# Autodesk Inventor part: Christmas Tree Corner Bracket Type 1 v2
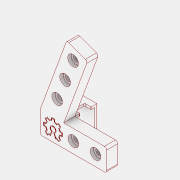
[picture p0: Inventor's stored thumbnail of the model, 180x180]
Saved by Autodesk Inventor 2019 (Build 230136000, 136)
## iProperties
Created: 2025-12
Part Number: Christmas Tree Corner Bracket Type 1 v2
Material: ABS Plastic
Document SubType Name: Modeling
Designer: sab
Density: 1.06 g/cm^3
Appearance: Red
Mass: 24.4978 g
Surface Area: 88.7218 cm^2
Volume: 23.1111 cm^3
Author: sab
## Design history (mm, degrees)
node "Blocks"
  sketch "Block1"
    geometry: L1 (0, 0.5)-(342.02, 940.193); L2 (0, -4.92)-(0, 0); L3 (0, -19.5)-(684.04, -19.5); L4 (21.284, 0.5)-(342.02, 881.717); L5 (0, 0.5)-(684.04, 0.5); L6 (662.757, 0.5)-(342.02, 881.717); L7 (684.04, 0.5)-(342.02, 940.193); L8 (684.04, -4.92)-(684.04, 0); L9 (0, 0.5)-(0, 0); L10 (684.04, 0.5)-(684.04, 0); 1 further point
    constraints: 20 end point
  sketch "Block1_1"
    geometry: L1 (-5.09, 2.943)-(-3.464, 3.257); L2 (-3.464, 3.257)-(-2.886, 4.652); L3 (-2.886, 4.652)-(-3.839, 6.061); L4 (-3.839, 6.061)-(-2.636, 7.264); L5 (-2.636, 7.264)-(-1.238, 6.318); L6 (-1.238, 6.318)-(0.22, 6.922); L7 (0.22, 6.922)-(0.531, 8.532); L8 (0.531, 8.532)-(2.267, 8.532); L9 (2.267, 8.532)-(2.588, 6.869); L10 (2.588, 6.869)-(4.046, 6.265); L11 (4.046, 6.265)-(5.403, 7.184); L12 (5.403, 7.184)-(6.631, 5.956); L13 (6.631, 5.956)-(5.682, 4.554); L14 (5.682, 4.554)-(6.286, 3.096); L15 (6.286, 3.096)-(7.895, 2.785); L16 (7.895, 2.785)-(7.895, 1.05); L17 (7.895, 1.05)-(6.232, 0.729); L18 (6.232, 0.729)-(5.627, -0.731); L19 (5.627, -0.731)-(6.541, -2.081); L20 (6.541, -2.081)-(5.344, -3.279); L21 (5.344, -3.279)-(3.887, -2.293); L22 (3.887, -2.293)-(3.329, -2.524); L23 (3.329, -2.524)-(2.197, 0.247); L24 (0.657, 0.303)-(-0.496, -2.521); L25 (-0.496, -2.521)-(-1.178, -2.239); L26 (-1.178, -2.239)-(-2.536, -3.157); L27 (-2.536, -3.157)-(-3.766, -1.927); L28 (-3.766, -1.927)-(-2.82, -0.529); L29 (-2.82, -0.529)-(-3.42, 0.919); L30 (-3.42, 0.919)-(-5.09, 1.242); L31 (-5.09, 1.242)-(-5.09, 2.943); A1 r 0.085 centre (-3.45, 3.333) between (-3.434, 3.25) and (-3.371, 3.301); A2 r 0.085 centre (-2.899, 4.663) between (-2.82, 4.63) and (-2.828, 4.711); A3 r 0.085 centre (-3.663, 6.098) between (-3.724, 6.158) and (-3.734, 6.05); A4 r 0.085 centre (-2.519, 7.242) between (-2.471, 7.312) and (-2.58, 7.302); A5 r 0.085 centre (-1.085, 6.477) between (-1.132, 6.407) and (-1.052, 6.398); A6 r 0.085 centre (0.245, 7.028) between (0.278, 6.949) and (0.329, 7.012); A7 r 0.085 centre (0.719, 8.583) between (0.719, 8.668) and (0.635, 8.599); A8 r 0.085 centre (2.337, 8.583) between (2.421, 8.599) and (2.337, 8.668); A9 r 0.085 centre (2.811, 7.028) between (2.727, 7.012) and (2.778, 6.949); A10 r 0.085 centre (4.14, 6.477) between (4.108, 6.398) and (4.188, 6.407); A11 r 0.085 centre (5.575, 7.242) between (5.636, 7.302) and (5.527, 7.312); A12 r 0.085 centre (6.719, 6.098) between (6.79, 6.05) and (6.78, 6.158); A13 r 0.085 centre (5.955, 4.663) between (5.884, 4.711) and (5.876, 4.63); A14 r 0.085 centre (6.506, 3.333) between (6.427, 3.301) and (6.489, 3.25); A15 r 0.085 centre (8.06, 2.859) between (8.146, 2.859) and (8.077, 2.943); A16 r 0.085 centre (8.06, 1.242) between (8.077, 1.158) and (8.146, 1.242); A17 r 0.085 centre (6.506, 0.768) between (6.489, 0.851) and (6.427, 0.8); A18 r 0.085 centre (5.955, -0.562) between (5.876, -0.529) and (5.884, -0.61); A19 r 0.085 centre (6.719, -1.997) between (6.78, -2.057) and (6.79, -1.949); A20 r 0.085 centre (5.575, -3.141) between (5.527, -3.212) and (5.636, -3.201); A21 r 0.085 centre (4.14, -2.376) between (4.188, -2.306) and (4.108, -2.297); A22 r 0.085 centre (3.466, -2.471) between (3.387, -2.503) and (3.499, -2.55); A23 r 0.085 centre (2.345, 0.274) between (2.31, 0.352) and (2.266, 0.242); A24 r 1.87 centre (1.489, 1.977) between (2.197, 0.247) and (0.657, 0.303); A25 r 0.085 centre (0.71, 0.274) between (0.79, 0.242) and (0.746, 0.352); A26 r 0.085 centre (-0.41, -2.471) between (-0.443, -2.55) and (-0.331, -2.503); A27 r 0.085 centre (-1.085, -2.376) between (-1.052, -2.297) and (-1.132, -2.306); A28 r 0.085 centre (-2.519, -3.141) between (-2.58, -3.201) and (-2.471, -3.212); A29 r 0.085 centre (-3.663, -1.997) between (-3.734, -1.949) and (-3.724, -2.057); A30 r 0.085 centre (-2.899, -0.562) between (-2.828, -0.61) and (-2.82, -0.529); A31 r 0.085 centre (-3.45, 0.768) between (-3.371, 0.8) and (-3.434, 0.851); A32 r 0.085 centre (-5.005, 1.242) between (-5.09, 1.242) and (-5.021, 1.158); A33 r 0.085 centre (-5.005, 2.859) between (-5.021, 2.943) and (-5.09, 2.859); 1 further point
    constraints: 66 point on circle, 62 end point, 33 centre point
  sketch "Block1_2"
    geometry: L1 (-0.89, -10)-(-0.68, -10.21); L2 (-0.89, -10)-(-0.68, -9.79); L3 (-0.68, -9.79)-(-0.68, -7.161); L4 (-0.68, -7.161)-(1.981, -4.5); L5 (1.981, -4.5)-(3.62, -4.5); L6 (3.62, -4.5)-(3.62, -6.875); L7 (3.62, -6.875)-(3.965, -6.875); L8 (3.965, -6.875)-(5.42, -5.42); L9 (5.42, -5.42)-(5.42, -0.5); L10 (4.92, 0)-(0, 0); L11 (-1.455, -1.455)-(0, 0); L12 (-1.455, -1.8)-(-1.455, -1.455); L13 (0.92, -1.8)-(-1.455, -1.8); L14 (0.92, -3.439)-(0.92, -1.8); L15 (-1.741, -6.1)-(0.92, -3.439); L16 (-4.37, -6.1)-(-1.741, -6.1); L17 (-4.58, -6.31)-(-4.37, -6.1); L18 (-4.58, -6.31)-(-4.79, -6.1); L19 (-4.79, -6.1)-(-7.419, -6.1); L20 (-7.419, -6.1)-(-10.08, -3.439); L21 (-10.08, -3.439)-(-10.08, -1.8); L22 (-10.08, -1.8)-(-7.705, -1.8); L23 (-7.705, -1.8)-(-7.705, -1.455); L24 (-7.705, -1.455)-(-9.16, 0); L25 (-9.16, 0)-(-14.08, 0); L26 (-14.58, -5.42)-(-14.58, -0.5); L27 (-13.125, -6.875)-(-14.58, -5.42); L28 (-12.78, -6.875)-(-13.125, -6.875); L29 (-12.78, -4.5)-(-12.78, -6.875); L30 (-11.141, -4.5)-(-12.78, -4.5); L31 (-8.48, -7.161)-(-11.141, -4.5); L32 (-8.48, -9.79)-(-8.48, -7.161); L33 (-8.27, -10)-(-8.48, -9.79); L34 (-8.27, -10)-(-8.48, -10.21); L35 (-8.48, -10.21)-(-8.48, -12.839); L36 (-8.48, -12.839)-(-11.141, -15.5); L37 (-11.141, -15.5)-(-12.78, -15.5); L38 (-12.78, -15.5)-(-12.78, -13.125); L39 (-12.78, -13.125)-(-13.125, -13.125); L40 (-13.125, -13.125)-(-14.58, -14.58); L41 (-14.58, -19.5)-(-14.58, -14.58); L42 (-9.16, -20)-(-14.08, -20); L43 (-7.705, -18.545)-(-9.16, -20); L44 (-7.705, -18.2)-(-7.705, -18.545); L45 (-10.08, -18.2)-(-7.705, -18.2); L46 (-10.08, -16.561)-(-10.08, -18.2); L47 (-7.419, -13.9)-(-10.08, -16.561); L48 (-4.79, -13.9)-(-7.419, -13.9); L49 (-4.58, -13.69)-(-4.79, -13.9); L50 (-4.58, -13.69)-(-4.37, -13.9); L51 (-4.37, -13.9)-(-1.741, -13.9); L52 (-1.741, -13.9)-(0.92, -16.561); L53 (0.92, -16.561)-(0.92, -18.2); L54 (0.92, -18.2)-(-1.455, -18.2); L55 (-1.455, -18.2)-(-1.455, -18.545); L56 (-1.455, -18.545)-(0, -20); L57 (4.92, -20)-(0, -20); L58 (5.42, -19.5)-(5.42, -14.58); L59 (3.965, -13.125)-(5.42, -14.58); L60 (3.62, -13.125)-(3.965, -13.125); L61 (3.62, -15.5)-(3.62, -13.125); L62 (1.981, -15.5)-(3.62, -15.5); L63 (-0.68, -12.839)-(1.981, -15.5); L64 (-0.68, -10.21)-(-0.68, -12.839)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; C1 r 2.1 at (-4.58, -10); A1 r 0.5 centre (4.92, -0.5) between (5.42, -0.5) and (4.92, 0); A2 r 0.5 centre (-14.08, -0.5) between (-14.08, 0) and (-14.58, -0.5); A3 r 0.5 centre (-14.08, -19.5) between (-14.58, -19.5) and (-14.08, -20); A4 r 0.5 centre (4.92, -19.5) between (4.92, -20) and (5.42, -19.5); A5 r 0.75 centre (4.92, -0.5) between (5.67, -0.5) and (4.92, 0.25); A6 r 0.75 centre (4.92, -19.5) between (4.92, -20.25) and (5.67, -19.5); A7 r 0.75 centre (-14.08, -19.5) between (-14.83, -19.5) and (-14.08, -20.25); A8 r 0.75 centre (-14.08, -0.5) between (-14.08, 0.25) and (-14.83, -0.5); 2 further points
    constraints: 256 end point, 16 point on circle, 9 centre point, 67 other
    dimensions: "d33" = 0.25 distance between parallel lines of L24 L65
sketch "Sketch1"
  geometry: L1 (0, 0)-(21.284, 0); L2 (60, 0)-(60, -20); L3 (60, -20)-(0, -20); L4 (0, -20)-(0, 0); L5 (0, 0)-(23.941, 65.778); L6 (23.941, 65.778)-(42.735, 58.938); L7 (42.735, 58.938)-(21.284, 0); L8 (18.794, -6.84)-(0, 0); L9 (21.284, 0)-(18.794, -6.84); L10 (21.284, 0)-(60, 0); L11 (0, -10)-(60, -10); L12 (33.338, 62.358)-(8.133, -2.96); 8 further points
  constraints: 24 end point, 6 parallel, 6 point on line, 4 midpoint, 3 horizontal, 3 perpendicular, 1 coincident, 6 other
  dimensions: "d0" = 60 distance of L2.end L3.end; "d1" = 70 distance of L5.start L5.end; "d2" = 30 distance from line of point (30, -10) L4 (= 0.5 x d0); "d3" = 20 distance of point (30, -10) point (10, -10); "d4" = 20 distance of point (30, -10) point (50, -10) (= d3); "d5" = 30 distance from line of point (22.536, 34.365) L6 (= d2); "d6" = 10 distance from line of L6 point (29.738, 53.027); "d7" = 20 distance from line of L8 point (15.334, 15.702); "d19" = 21.28356 distance from line of L1.end L4
  node "Block1:1" dims "d0" = 60, "d1" = 70, "d2" = 30 (= 0.5 x d0), "d3" = 20, "d4" = 20 (= d3), "d5" = 30 (= d2), "d6" = 10, "d7" = 20, "d19" = 21.28356
  node "Block2:1" dims "d0" = 60, "d1" = 70, "d2" = 30 (= 0.5 x d0), "d3" = 20, "d4" = 20 (= d3), "d5" = 30 (= d2), "d6" = 10, "d7" = 20, "d19" = 21.28356
extrude "Extrusion1" new body sketch "Sketch1" distance "d8" = 10; taper "d9" = 0 deg
hole "Hole1" sketch "Sketch1" diameter "d10" = 5.4; stored, may be unused: countersink angle "d14" = 90 deg, drill point angle "d16" = 118 deg; dims "d11" = 12.7, "d12" = 9.5, "d13" = 3, "d15" = 8
emboss "Emboss1" sketch "Sketch1" dims "d5" = 30 (= d2), "d17" = 0.3, "d18" = 0
fillet "Fillet1" dims "d21" = 2
sketch "Sketch2"
  geometry: L1 (-42.051, 57.059)-(-21.284, 0) reference; L2 (-21.284, 0)-(-58, 0) reference; L3 (-60, -2)-(-60, -18) reference; L4 (-58, -20)-(-2, -20) reference; L5 (0, -18)-(0, -0.353) reference; L6 (-0.121, 0.331)-(-23.257, 63.899) reference; L7 (-25.821, 65.094)-(-40.856, 59.622) reference; L8 (-21.284, 0)-(0, 0); L9 (0, 0)-(0, -20); L10 (0, -20)-(-21.284, -20); L11 (-21.284, -20)-(-21.284, 0); C1 r 2.7 at (-29.738, 53.027) reference; C2 r 2.7 at (-50, -10) reference; C3 r 2.7 at (-30, -10) reference; C4 r 2.7 at (-22.536, 34.365) reference; C5 r 2.7 at (-15.334, 15.702) reference; A1 r 2 centre (-40.172, 57.743) between (-40.856, 59.622) and (-42.051, 57.059) reference; A2 r 2 centre (-58, -2) between (-58, 0) and (-60, -2) reference; A3 r 2 centre (-58, -18) between (-60, -18) and (-58, -20) reference; A4 r 2 centre (-2, -18) between (-2, -20) and (0, -18) reference; A5 r 2 centre (-2, -0.353) between (0, -0.353) and (-0.121, 0.331) reference; A6 r 2 centre (-25.137, 63.215) between (-23.257, 63.899) and (-25.821, 65.094) reference; 1 further point
  constraints: 8 end point, 2 parallel, 1 horizontal, 1 perpendicular
extrude "Extrusion2" join sketch "Sketch2" distance "d22" = 20; taper "d23" = 0 deg
fillet "Fillet2" dims "d24" = 2
sketch "Sketch3"
  geometry: L1 (0, 0)-(-21.284, 0) reference; L2 (-21.284, 0)-(-21.284, -20) reference
emboss "Emboss2" sketch "Sketch3" dims "d5" = 30 (= d2), "d25" = 0.3, "d26" = 0
sketch "Sketch4"
  geometry: L1 (0, 20)-(0, 18) reference; L2 (-10, 2)-(20, 2) reference; L3 (0, 18)-(18, 18); L4 (18, 18)-(18, 2); L5 (18, 2)-(0, 2); L6 (0, 2)-(0, 18); 1 further point
  constraints: 8 end point, 2 parallel, 1 horizontal, 1 perpendicular, 1 point on line
  dimensions: "d29" = 18 distance of L4.end L5.end
extrude "Extrusion3" cut sketch "Sketch4" distance "d30" = 18; taper "d31" = 0 deg
fillet "Fillet3" dims "d32" = 0.5
sketch "Sketch5"
  geometry: L1 (20.784, 20)-(0, 20); L2 (0, 0)-(0, 20); L3 (0, 0)-(21.252, 0); L4 (21.284, 0)-(21.252, 0); L5 (21.284, 0)-(21.284, 19.5); L6 (0, 18)-(0, 0); L7 (0, 13.85)-(6, 13.85); L8 (6, 13.85)-(6, 5.6); L9 (6, 5.6)-(0, 5.6); L10 (0, 5.6)-(0, 13.85); L11 (21.252, 0)-(21.252, 19.5) reference; L12 (21.284, 4.754)-(15.284, 4.754); L13 (15.284, 4.754)-(15.284, 14.754); L14 (15.284, 14.754)-(21.284, 14.754); L15 (21.284, 14.754)-(21.284, 4.754); L16 (14.316, 9.75)-(24.523, 9.75); L17 (15.284, 14.754)-(21.284, 4.754); L18 (21.284, 14.754)-(15.284, 4.754); A1 r 0.5 centre (20.784, 19.5) between (21.284, 19.5) and (20.784, 20); 3 further points
  constraints: 34 end point, 4 parallel, 3 horizontal, 2 perpendicular, 2 point on circle, 1 centre point, 1 midpoint, 1 point on line, 2 other
  dimensions: "d34" = 6 distance of L8.end L9.end; "d35" = 6 distance of L13.end L14.end; "d39" = 10 distance between parallel lines of L12 L14
extrude "Extrusion4" cut sketch "Sketch5" distance "d36" = 10; taper "d37" = 0 deg
fillet "Fillet4" dims "d38" = 0.5
body "Solid1"
node "Projected Loop1"
sketch "Block2"
  geometry: L1 (-78.347, -9.505)-(-78.347, -12.199); L2 (-78.347, -12.199)-(-76.112, -12.63); L3 (-76.112, -12.63)-(-75.466, -14.191); L4 (-75.466, -14.191)-(-76.732, -16.063); L5 (-76.732, -16.063)-(-74.792, -18.002); L6 (-74.792, -18.002)-(-72.972, -16.771); L7 (-72.972, -16.771)-(-71.963, -17.189); L8 (-71.963, -17.189)-(-70.249, -12.99); L9 (-69.071, -13.039)-(-67.375, -17.193); L10 (-67.375, -17.193)-(-66.525, -16.84); L11 (-66.525, -16.84)-(-64.577, -18.158); L12 (-64.577, -18.158)-(-62.68, -16.261); L13 (-62.68, -16.261)-(-63.905, -14.45); L14 (-63.905, -14.45)-(-63.253, -12.876); L15 (-63.253, -12.876)-(-61.026, -12.446); L16 (-61.026, -12.446)-(-61.026, -9.709); L17 (-61.026, -9.709)-(-63.183, -9.293); L18 (-63.183, -9.293)-(-63.835, -7.72); L19 (-63.835, -7.72)-(-62.565, -5.843); L20 (-62.565, -5.843)-(-64.501, -3.907); L21 (-64.501, -3.907)-(-66.32, -5.138); L22 (-66.32, -5.138)-(-67.893, -4.486); L23 (-67.893, -4.486)-(-68.322, -2.261); L24 (-68.322, -2.261)-(-71.06, -2.261); L25 (-71.06, -2.261)-(-71.477, -4.418); L26 (-71.477, -4.418)-(-73.049, -5.069); L27 (-73.049, -5.069)-(-74.921, -3.803); L28 (-74.921, -3.803)-(-76.826, -5.708); L29 (-76.826, -5.708)-(-75.55, -7.593); L30 (-75.55, -7.593)-(-76.168, -9.085); L31 (-76.168, -9.085)-(-78.347, -9.505); L32 (-75.73, -9.622)-(-77.736, -10.009); L33 (-77.736, -10.009)-(-77.736, -11.695); L34 (-77.736, -11.695)-(-75.674, -12.093); L35 (-75.674, -12.093)-(-74.776, -14.261); L36 (-74.776, -14.261)-(-75.943, -15.987); L37 (-75.943, -15.987)-(-74.717, -17.214); L38 (-74.717, -17.214)-(-73.042, -16.08); L39 (-73.042, -16.08)-(-72.297, -16.389); L40 (-72.297, -16.389)-(-71.03, -13.288); L41 (-68.273, -13.378)-(-67.041, -16.393); L42 (-67.041, -16.393)-(-66.455, -16.15); L43 (-66.455, -16.15)-(-64.653, -17.369); L44 (-64.653, -17.369)-(-63.468, -16.185); L45 (-63.468, -16.185)-(-64.595, -14.52); L46 (-64.595, -14.52)-(-63.691, -12.338); L47 (-63.691, -12.338)-(-61.637, -11.942); L48 (-61.637, -11.942)-(-61.637, -10.213); L49 (-61.637, -10.213)-(-63.622, -9.83); L50 (-63.622, -9.83)-(-64.525, -7.65); L51 (-64.525, -7.65)-(-63.353, -5.918); L52 (-63.353, -5.918)-(-64.576, -4.695); L53 (-64.576, -4.695)-(-66.25, -5.828); L54 (-66.25, -5.828)-(-68.43, -4.925); L55 (-68.43, -4.925)-(-68.826, -2.872); L56 (-68.826, -2.872)-(-70.556, -2.872); L57 (-70.556, -2.872)-(-70.939, -4.856); L58 (-70.939, -4.856)-(-73.119, -5.759); L59 (-73.119, -5.759)-(-74.845, -4.591); L60 (-74.845, -4.591)-(-76.037, -5.783); L61 (-76.037, -5.783)-(-74.86, -7.523); L62 (-74.86, -7.523)-(-75.73, -9.622); L63 (-78.042, -11.948)-(-78.042, -9.757); L64 (-78.042, -9.757)-(-75.95, -9.353)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; A1 r 2.101 centre (-69.575, -11) between (-69.071, -13.039) and (-70.249, -12.99); A2 r 2.711 centre (-69.575, -11) between (-68.273, -13.378) and (-71.03, -13.288); A3 r 2.406 centre (-69.575, -11) between (-68.665, -13.227) and (-70.645, -13.154); 1 further point
  constraints: 186 end point, 6 point on circle, 3 centre point, 62 other
  dimensions: "d27" = 0.305 distance between parallel lines of L63 L1; "d28" = 0.3058 distance between parallel lines of L64 L32
node "Block1_1:2"
node "Block1_2:1" dims "d34" = 6
